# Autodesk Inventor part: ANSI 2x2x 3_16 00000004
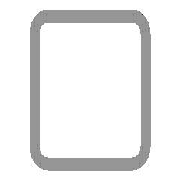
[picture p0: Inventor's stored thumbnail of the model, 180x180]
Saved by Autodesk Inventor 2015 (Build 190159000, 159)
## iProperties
IsCustomPart: 1
Created: 2007-02
Part Number: ANSI 2x2x 3_16 00000004
Material: Steel
Document SubType Name: Modeling
Standard: AISC
Designer: Autodesk, Inc.
Size Designation: 2x2x3/16
Stock Number: 2x2x 3/16
Density: 7.85 g/cm^3
Description: Tube
Standards Organization: ANSI
Language: en-US
Categories: <MemberInstance><Categories><Category DisplayName="Structural Shapes" InternalName="089c4875-fa83-4c05-b084-43b9cc11f5ed" Mnemonic="GRDR"><CategoryParameter Dis
Mass: 3346.04 g
Surface Area: 1806.39 cm^2
Volume: 426.248 cm^3
Appearance: Steel
G_L: 20.500 in
G_W: 2.000 in
G_H: 2.000 in
+7A73AECC-8F9B-4983-91A2-8C1CC56858A4+CUTDETAIL1: Cut
+BB0950B5-2B19-488D-A3DB-6CFB48C1EDDC+CUTDETAIL2: Cut
_FrameMemberDoc: Frame Member File
_Version: 15.0.0
_CCFamilyMember: 1
_CCFamilyDisplayName: ANSI AISC (Square) - Tube
Author: Autodesk, Inc.
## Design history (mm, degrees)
node "Start plane"
node "End plane"
sketch "Sketch"
  geometry: L1 (-25.4, -15.875)-(-25.4, 15.875); L2 (-15.875, 25.4)-(15.875, 25.4); L3 (25.4, 15.875)-(25.4, -15.875); L4 (15.875, -25.4)-(-15.875, -25.4); L5 (-15.875, 20.637)-(15.875, 20.638); L6 (20.637, 15.875)-(20.637, -15.875); L7 (15.875, -20.637)-(-15.875, -20.638); L8 (-20.637, -15.875)-(-20.637, 15.875); L9 (0, 38.322)-(0, -38.322) reference; L10 (-38.322, 0)-(38.322, 0) reference; A1 r 9.525 centre (-15.875, -15.875) between (-25.4, -15.875) and (-15.875, -25.4); A2 r 9.525 centre (-15.875, 15.875) between (-15.875, 25.4) and (-25.4, 15.875); A3 r 9.525 centre (15.875, 15.875) between (25.4, 15.875) and (15.875, 25.4); A4 r 9.525 centre (15.875, -15.875) between (15.875, -25.4) and (25.4, -15.875); A5 r 4.762 centre (-15.875, 15.875) between (-15.875, 20.637) and (-20.637, 15.875); A6 r 4.762 centre (15.875, 15.875) between (20.637, 15.875) and (15.875, 20.638); A7 r 4.762 centre (15.875, -15.875) between (15.875, -20.637) and (20.637, -15.875); A8 r 4.762 centre (-15.875, -15.875) between (-20.637, -15.875) and (-15.875, -20.638)
  constraints: 16 end point, 16 point on circle, 8 centre point, 8 tangent, 4 parallel, 3 equal radius, 2 perpendicular, 7 other
  dimensions: "d10" = 50.8 distance between parallel lines of L2 L4 (= G_H); "d11" = 50.8 distance between parallel lines of L1 L3 (= G_W); "d12" = 4.7625 distance between parallel lines of L3 L6 (= G_T); "d15" = 25.4 distance between parallel lines of L2 L10 (= 0.5 x d10); "d16" = 25.4 distance between parallel lines of L9 L3 (= 0.5 x d11); "d17" = 9.525 radius of A1 (= G_IR)
extrude "Body" new body sketch "Sketch" stored distance "d3" = 520.7 (= G_L); taper "d4" = 0 deg
node "Driven Length"
  sketch "Sketch3"
    geometry: L1 (0, 0)-(10, 0) reference
    constraints: 2 end point, 1 horizontal
  workplane "Work Plane5"
  sketch "Sketch4"
    geometry: L1 (-2, -6.35)-(12, -6.35) reference; L2 (-2, 514.35)-(12, 514.35) reference
    dimensions: "d19" = 520.7 distance between parallel lines of L1 L2 (derived)
workplane "Work Plane3"
split "Split1"
workplane "Work Plane4"
split "Split2"
body "Solid1"
other parameters: "G_W" = 50.8 [user parameter; used in 1 equation term], "G_H" = 50.8 [user parameter; used in 1 equation term], "G_T" = 4.7625 [user parameter; used in 1 equation term], "G_IR" = 9.525 [user parameter; used in 1 equation term], "G_L" = 520.7 (= d19) [user parameter; used in 1 equation term], "G_OFFSET_START" = 6.35 [user parameter; used in 1 equation term], "G_OFFSET_END" = 6.35 [user parameter; used in 1 equation term], "d13" = -6.35 (= -G_OFFSET_START), "d14" = 514.35 (= G_OFFSET_END + B_L), "B_L" = 508 [user parameter; used in 1 equation term], "d18" = 90 deg
